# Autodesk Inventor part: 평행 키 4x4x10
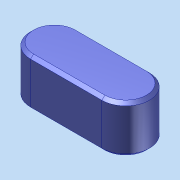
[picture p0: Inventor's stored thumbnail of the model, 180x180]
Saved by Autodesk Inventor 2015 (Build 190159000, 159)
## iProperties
Created: 2026-09
Part Number: 평행 키 4x4x10
Material: 일반
Document SubType Name: Modeling
Designer: SCD-A06
Density: 1 g/cm^3
Appearance: 기본값
Author: SCD-A06
Author: jhkim
Description: 키 및 해당 키홈
Creation Date: 2026-08-27
Sending System: Autodesk Inventor 2027
Preprocessor: ST-DEVELOPER v20.1
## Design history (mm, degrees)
node "평행 키 4x4x101"
body "Solid1"
node "기준1"
